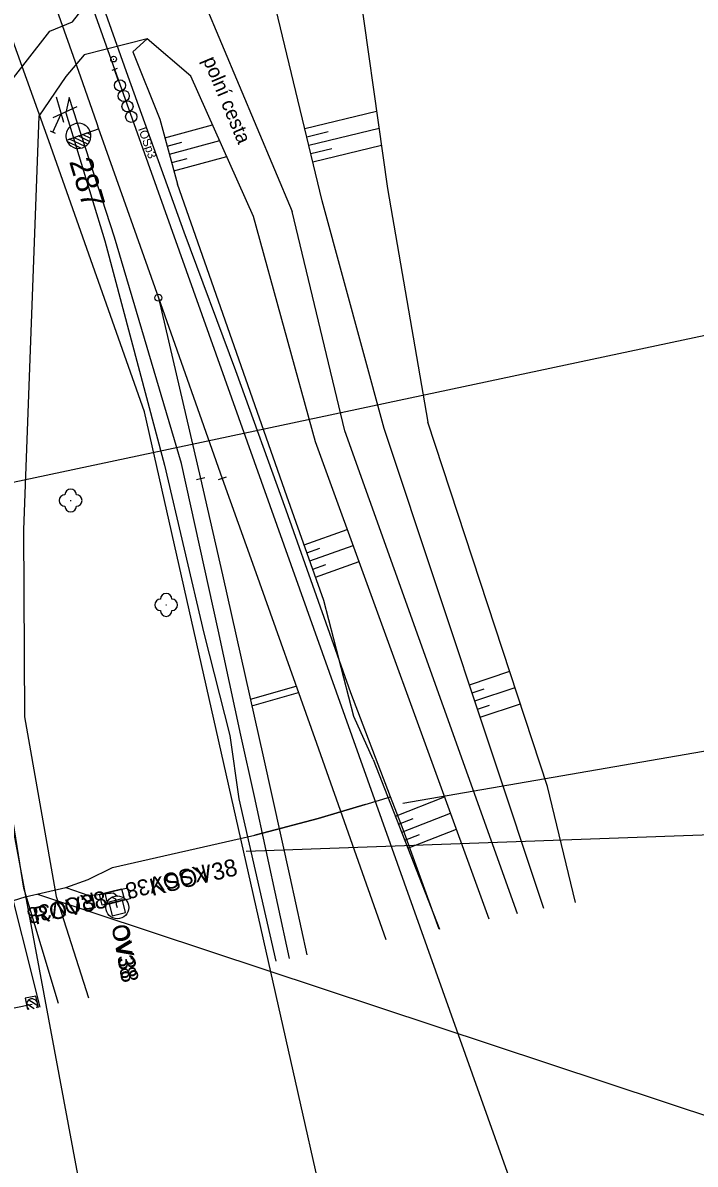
# Model space of a CAD drawing. Extents: x -545967 to -545044, y -1122650 to -1118491.
# Drawn here: x -545696.6 to -545637.8, y -1119258 to -1119158.2 of the extents above; entities that cross this region are included whole.
import ezdxf

# ---------------------------------------------------------------- set-up
doc = ezdxf.new("R2010")
doc.units = 0
for name, color, linetype in [('osvětlené plochy-hodnota-obrys', 7, 'Continuous'), ('Vrstva 1', 7, 'Continuous'), ('Vrstva 11', 7, 'Continuous'), ('Vrstva 11 - Trakce', 7, 'Continuous'), ('Vrstva 12', 7, 'Continuous'), ('Vrstva 12 - Trakce zaklady', 7, 'Continuous'), ('Vrstva 2', 7, 'Continuous'), ('Vrstva 25', 7, 'Continuous'), ('Vrstva 25 - silnoproud prvky', 7, 'Continuous'), ('Vrstva 26', 7, 'Continuous'), ('Vrstva 26 - silnoproud', 7, 'Continuous'), ('Vrstva 28', 7, 'Continuous'), ('Vrstva 4', 7, 'Continuous'), ('Vrstva 48', 7, 'Continuous'), ('Vrstva 49', 7, 'Continuous'), ('Vrstva 50', 7, 'Continuous'), ('Vrstva 51', 7, 'Continuous'), ('Vrstva 6', 7, 'Continuous'), ('Vrstva 63', 7, 'Continuous'), ('Vrstva 7', 7, 'Continuous')]:
    doc.layers.add(name, color=color, linetype=linetype)

msp = doc.modelspace()

# ---------------------------------------------------------------- linework, layer by layer
at = {"layer": 'osvětlené plochy-hodnota-obrys'}
for points in [[(-545694.33, -1119168.5), (-545707.92, -1119130.607), (-545700.794, -1119127.991)], [(-545700.794, -1119127.991), (-545610.463, -1119381.573), (-545628.868, -1119385.178)], [(-545700.341, -1119250.428), (-545705.955, -1119221.665), (-545699.039, -1119220.315), (-545660.607, -1119425.918), (-545653.752, -1119372.856), (-545653.095, -1119348.321), (-545657.119, -1119319.988), (-545685.945, -1119192.198), (-545694.33, -1119168.5)]]:
    msp.add_lwpolyline(points, dxfattribs=at)
at = {"layer": 'Vrstva 1'}
for points in [[(-545730.526, -1119049.438), (-545727.173, -1119060.47), (-545720.468, -1119081.174), (-545711.793, -1119106.078), (-545703.851, -1119128.397), (-545698.023, -1119144.665), (-545693.948, -1119156.135), (-545691.544, -1119162.895), (-545690.154, -1119166.896), (-545689.961, -1119167.438), (-545689.699, -1119168.179), (-545684.737, -1119182.215), (-545679.147, -1119198.024), (-545676.369, -1119205.846), (-545670.918, -1119221.162), (-545664.828, -1119238.335)], [(-545684.737, -1119182.215), (-545681.048, -1119198.017), (-545679.115, -1119206.463), (-545675.534, -1119222.463), (-545673.245, -1119232.849), (-545671.741, -1119239.689)]]:
    msp.add_lwpolyline(points, dxfattribs=at)
at = {"layer": 'Vrstva 11'}
for points in [[(-545693.484, -1119243.944), (-545696.51, -1119233.839), (-545699.129, -1119217.635), (-545699.471, -1119201.94)], [(-545696.533, -1119202.507), (-545696.456, -1119218.879), (-545693.686, -1119234.563), (-545690.855, -1119243.429)]]:
    msp.add_lwpolyline(points, dxfattribs=at)
at = {"layer": 'Vrstva 11 - Trakce'}
for p, q in [((-545695.782, -1119244.029), (-545712.397, -1119247.251)), ((-545696.269, -1119243.934), (-545695.596, -1119244.357)), ((-545696.064, -1119243.62), (-545695.29, -1119244.107))]:
    msp.add_line(p, q, dxfattribs=at)
msp.add_arc((-545695.782, -1119244.029), 0.5, 325.36376, 236.78364, dxfattribs=at)
at = {"layer": 'Vrstva 12'}
msp.add_lwpolyline([(-545687.603, -1119235.974), (-545687.894, -1119234.788), (-545689.08, -1119235.079), (-545688.789, -1119236.265), (-545687.603, -1119235.974)], dxfattribs=at)
at = {"layer": 'Vrstva 12 - Trakce zaklady'}
for points in [[(-545687.603, -1119235.974), (-545687.894, -1119234.788), (-545689.08, -1119235.079), (-545688.789, -1119236.265), (-545687.603, -1119235.974)], [(-545695.23, -1119244.286), (-545695.454, -1119243.299), (-545696.392, -1119243.46)], [(-545696.392, -1119243.46), (-545696.174, -1119244.47)]]:
    msp.add_lwpolyline(points, dxfattribs=at)
at = {"layer": 'Vrstva 2'}
for p, q in [((-545692.765, -1119168.432), (-545690.695, -1119167.7)), ((-545692.764, -1119168.433), (-545692.765, -1119168.432)), ((-545692.76, -1119168.438), (-545689.961, -1119167.438)), ((-545691.148, -1119168.994), (-545692.512, -1119168.343)), ((-545690.909, -1119168.792), (-545692.132, -1119168.208)), ((-545690.749, -1119168.553), (-545691.752, -1119168.074)), ((-545690.655, -1119168.282), (-545691.372, -1119167.94)), ((-545690.638, -1119167.974), (-545690.992, -1119167.805)), ((-545691.505, -1119169.139), (-545692.704, -1119168.567)), ((-545684.737, -1119182.215), (-545681.048, -1119198.017)), ((-545681.414, -1119198.099), (-545680.682, -1119197.935)), ((-545678.794, -1119197.898), (-545679.5, -1119198.15))]:
    msp.add_line(p, q, dxfattribs=at)
msp.add_lwpolyline([(-545689.961, -1119167.438), (-545689.699, -1119168.179), (-545684.737, -1119182.215), (-545679.147, -1119198.024)], dxfattribs=at)
msp.add_circle((-545684.737, -1119182.215), 0.3, dxfattribs=at)
for centre, radius, start, end in [((-545691.729, -1119168.065), 1.097, 19.42224, 199.89176), ((-545691.729, -1119168.066), 1.098, 199.51177, 19.47262)]:
    msp.add_arc(centre, radius, start, end, dxfattribs=at)
at = {"layer": 'Vrstva 25'}
for points in [[(-545689.652, -1119235.344), (-545689.89, -1119234.373), (-545687.948, -1119233.896), (-545687.71, -1119234.867), (-545689.652, -1119235.344)], [(-545687.448, -1119233.816), (-545687.21, -1119234.787), (-545689.152, -1119235.264), (-545689.39, -1119234.293), (-545687.448, -1119233.816)]]:
    msp.add_lwpolyline(points, dxfattribs=at)
msp.add_circle((-545688.326, -1119235.53), 1, dxfattribs=at)
at = {"layer": 'Vrstva 25 - silnoproud prvky'}
for points in [[(-545689.652, -1119235.344), (-545689.89, -1119234.373), (-545687.948, -1119233.896), (-545687.71, -1119234.867), (-545689.652, -1119235.344)], [(-545687.448, -1119233.816), (-545687.21, -1119234.787), (-545689.152, -1119235.264), (-545689.39, -1119234.293), (-545687.448, -1119233.816)]]:
    msp.add_lwpolyline(points, dxfattribs=at)
msp.add_circle((-545688.326, -1119235.53), 1, dxfattribs=at)
at = {"layer": 'Vrstva 26'}
for points in [[(-545660.174, -1119237.425), (-545663.331, -1119228.723), (-545664.431, -1119225.855), (-545667.915, -1119216.776), (-545673.57, -1119200.8), (-545677.95, -1119188.599), (-545682.479, -1119176.492), (-545687.385, -1119162.872), (-545691.436, -1119151.431), (-545691.75, -1119150.64)], [(-545687.385, -1119162.872), (-545691.436, -1119151.431)], [(-545698.841, -1119235.301), (-545698.529, -1119235.274), (-545696.399, -1119234.598), (-545692.825, -1119233.775), (-545690.864, -1119233.076), (-545688.738, -1119232.03), (-545676.291, -1119229.209), (-545675.638, -1119229.038), (-545670.747, -1119227.759), (-545668.794, -1119227.17), (-545666.647, -1119226.523), (-545664.431, -1119225.855)], [(-545666.647, -1119226.523), (-545668.794, -1119227.17), (-545670.747, -1119227.759), (-545675.638, -1119229.038), (-545676.291, -1119229.209)], [(-545692.825, -1119233.775), (-545690.82, -1119234.48), (-545688.66, -1119234.25), (-545688.3, -1119234.54), (-545688.8, -1119234.62), (-545688.49, -1119234.77), (-545688.44, -1119235.29), (-545688.326, -1119235.529), (-545688.326, -1119235.53)]]:
    msp.add_lwpolyline(points, dxfattribs=at)
at = {"layer": 'Vrstva 26 - silnoproud'}
for points in [[(-545660.174, -1119237.425), (-545663.331, -1119228.723), (-545664.431, -1119225.855), (-545667.915, -1119216.776), (-545673.57, -1119200.8), (-545677.95, -1119188.599), (-545682.479, -1119176.492), (-545687.385, -1119162.872), (-545691.436, -1119151.431), (-545691.75, -1119150.64)], [(-545687.385, -1119162.872), (-545691.436, -1119151.431)], [(-545708.67, -1119197.64), (-545708.32, -1119197.58), (-545708.6, -1119196.51), (-545704.54, -1119197.6), (-545702.23, -1119206.95), (-545699.9, -1119221.45), (-545698.219, -1119231.843), (-545695.098, -1119244.26)], [(-545698.841, -1119235.301), (-545698.529, -1119235.274), (-545696.399, -1119234.598), (-545692.825, -1119233.775), (-545690.864, -1119233.076), (-545688.738, -1119232.03), (-545676.291, -1119229.209), (-545675.638, -1119229.038), (-545670.747, -1119227.759), (-545668.794, -1119227.17), (-545666.647, -1119226.523), (-545664.431, -1119225.855)], [(-545666.647, -1119226.523), (-545668.794, -1119227.17), (-545670.747, -1119227.759), (-545675.638, -1119229.038), (-545676.291, -1119229.209)], [(-545692.825, -1119233.775), (-545690.82, -1119234.48), (-545688.66, -1119234.25), (-545688.3, -1119234.54), (-545688.8, -1119234.62), (-545688.49, -1119234.77), (-545688.44, -1119235.29), (-545688.326, -1119235.529), (-545688.326, -1119235.53)]]:
    msp.add_lwpolyline(points, dxfattribs=at)
at = {"layer": 'Vrstva 28'}
msp.add_line((-545688.678, -1119161.351), (-545688.628, -1119161.351), dxfattribs=at)
msp.add_circle((-545688.653, -1119161.351), 0.25, dxfattribs=at)
at = {"layer": 'Vrstva 4'}
for p, q in [((-545693.948, -1119156.135), (-545691.544, -1119162.895)), ((-545693.667, -1119164.657), (-545693.034, -1119166.873)), ((-545693.978, -1119167.733), (-545693.248, -1119166.142)), ((-545693.943, -1119166.457), (-545691.85, -1119165.491)), ((-545694.205, -1119167.629), (-545693.751, -1119167.837))]:
    msp.add_line(p, q, dxfattribs=at)
for points in [[(-545682.722, -1119196.715), (-545688.56, -1119176.928), (-545692.538, -1119164.711), (-545692.829, -1119166.04), (-545689.41, -1119177.241), (-545684.189, -1119196.85), (-545680.751, -1119211.563), (-545678.475, -1119220.498)], [(-545673.268, -1119239.987), (-545676.336, -1119225.824), (-545677.525, -1119220.471), (-545679.503, -1119211.27), (-545682.722, -1119196.715)], [(-545678.475, -1119220.498), (-545677.708, -1119226.035), (-545674.475, -1119240.224)]]:
    msp.add_lwpolyline(points, dxfattribs=at)
at = {"layer": 'Vrstva 48'}
for p, q in [((-545671.927, -1119167.414), (-545665.647, -1119165.898)), ((-545684.16, -1119168.233), (-545679.991, -1119167.099)), ((-545671.574, -1119168.872), (-545665.435, -1119167.39)), ((-545671.75, -1119168.143), (-545669.888, -1119167.693)), ((-545683.963, -1119168.956), (-545682.679, -1119168.607)), ((-545683.766, -1119169.68), (-545679.373, -1119168.485)), ((-545671.398, -1119169.601), (-545669.577, -1119169.162)), ((-545671.222, -1119170.33), (-545665.222, -1119168.881)), ((-545683.569, -1119170.404), (-545682.218, -1119170.036)), ((-545683.372, -1119171.128), (-545678.755, -1119169.872)), ((-545671.995, -1119203.823), (-545668.209, -1119202.472)), ((-545671.743, -1119204.529), (-545670.606, -1119204.124)), ((-545671.491, -1119205.236), (-545667.696, -1119203.882)), ((-545670.987, -1119206.649), (-545667.183, -1119205.292)), ((-545671.239, -1119205.942), (-545670.099, -1119205.536)), ((-545657.535, -1119216.057), (-545654.01, -1119214.886)), ((-545657.062, -1119217.48), (-545653.542, -1119216.311)), ((-545657.298, -1119216.769), (-545656.242, -1119216.418)), ((-545656.826, -1119218.192), (-545655.77, -1119217.842)), ((-545656.589, -1119218.904), (-545653.074, -1119217.736)), ((-545664.001, -1119227.551), (-545659.699, -1119225.869)), ((-545663.455, -1119228.948), (-545659.186, -1119227.279)), ((-545663.728, -1119228.249), (-545662.442, -1119227.747)), ((-545663.182, -1119229.646), (-545661.906, -1119229.148)), ((-545662.909, -1119230.345), (-545658.673, -1119228.689))]:
    msp.add_line(p, q, dxfattribs=at)
at = {"layer": 'Vrstva 49'}
for points in [[(-545675.226, -1119153.753), (-545667.594, -1119152.222), (-545664.683, -1119172.67), (-545661.167, -1119193.097)], [(-545651.031, -1119235.635), (-545664.976, -1119193.655), (-545670.399, -1119173.739), (-545675.226, -1119153.753)], [(-545685.704, -1119159.567), (-545686.973, -1119160.727), (-545684.605, -1119166.595), (-545683.057, -1119172.287)], [(-545655.806, -1119236.57), (-545670.996, -1119194.81), (-545676.417, -1119175.121), (-545681.891, -1119162.833), (-545685.704, -1119159.567)], [(-545665.935, -1119222.602), (-545667.654, -1119218.849), (-545670.261, -1119208.684), (-545673.512, -1119199.57), (-545683.057, -1119172.287)], [(-545648.239, -1119235.089), (-545650.699, -1119224.967), (-545661.167, -1119193.097)], [(-545665.935, -1119222.602), (-545660.145, -1119237.419)]]:
    msp.add_lwpolyline(points, dxfattribs=at)
at = {"layer": 'Vrstva 50'}
for p, q in [((-545692.439, -1119199.95), (-545692.368, -1119199.95)), ((-545684.084, -1119209.08), (-545684.012, -1119209.08))]:
    msp.add_line(p, q, dxfattribs=at)
for centre, start, end in [((-545692.41, -1119199.449), 0, 180), ((-545692.91, -1119199.949), 90, 270), ((-545691.91, -1119199.949), 270, 90), ((-545692.41, -1119200.449), 180, 0), ((-545684.054, -1119208.579), 0, 180), ((-545684.554, -1119209.079), 90, 270), ((-545683.554, -1119209.079), 270, 90), ((-545684.054, -1119209.579), 180, 0)]:
    msp.add_arc(centre, 0.5, start, end, dxfattribs=at)
at = {"layer": 'Vrstva 51'}
for points in [[(-545699.471, -1119201.94), (-545698.549, -1119164.446), (-545694.235, -1119158.917), (-545692.241, -1119158.084), (-545688.341, -1119153.091), (-545685.062, -1119149.37), (-545681.978, -1119143.375)], [(-545679.27, -1119144.734), (-545681.865, -1119150.517), (-545680.757, -1119156.324), (-545673.045, -1119174.666)], [(-545676.417, -1119175.121), (-545681.891, -1119162.833), (-545685.704, -1119159.567), (-545691.222, -1119160.972), (-545692.83, -1119162.884), (-545695.181, -1119166.34), (-545696.533, -1119202.507)], [(-545655.806, -1119236.57), (-545670.996, -1119194.81), (-545676.417, -1119175.121)], [(-545653.315, -1119236.082), (-545668.43, -1119193.867), (-545673.045, -1119174.666)]]:
    msp.add_lwpolyline(points, dxfattribs=at)
at = {"layer": 'Vrstva 6'}
for p, q in [((-545688.35, -1119162.184), (-545688.821, -1119162.351)), ((-545688.253, -1119163.2), (-545688.585, -1119162.268))]:
    msp.add_line(p, q, dxfattribs=at)
for centre in [(-545688.09, -1119163.657), (-545687.763, -1119164.572), (-545687.437, -1119165.486), (-545687.111, -1119166.401)]:
    msp.add_circle(centre, 0.486, dxfattribs=at)
at = {"layer": 'Vrstva 63'}
for p, q in [((-545607.451, -1119179.265), (-545702.192, -1119199.374)), ((-545600.352, -1119215.539), (-545663.35, -1119226.444)), ((-545597.957, -1119227.774), (-545677.045, -1119230.655)), ((-545589.819, -1119269.354), (-545695.286, -1119234.415))]:
    msp.add_line(p, q, dxfattribs=at)
at = {"layer": 'Vrstva 7'}
for p, q in [((-545676.683, -1119217.329), (-545672.692, -1119216.177)), ((-545676.552, -1119217.916), (-545672.491, -1119216.743))]:
    msp.add_line(p, q, dxfattribs=at)

# ---------------------------------------------------------------- texts
at = {"layer": 'Vrstva 2'}
msp.add_text('287', height=2, rotation=286.78427, dxfattribs=at).set_placement((-545692.554, -1119170.3))
at = {"layer": 'Vrstva 25'}
for s, rotation, p in [('KSOV38', 13.7859, (-545685.285, -1119234.54)), ('ROV38', 13.7859, (-545695.496, -1119237.047)), ('OV38', 280.61663, (-545688.844, -1119237.154))]:
    msp.add_text(s, height=1.5, rotation=rotation, dxfattribs=at).set_placement(p)
at = {"layer": 'Vrstva 25 - silnoproud prvky'}
for s, rotation, p in [('KSOV38', 193.7859, (-545680.65, -1119231.731)), ('ROV38', 193.7859, (-545690.382, -1119234.182)), ('OV38', 280.61663, (-545688.844, -1119237.154))]:
    msp.add_text(s, height=1.4, rotation=rotation, dxfattribs=at).set_placement(p)
at = {"layer": 'Vrstva 51'}
msp.add_text('polní cesta', height=1.25, rotation=292.8046, dxfattribs=at).set_placement((-545680.862, -1119161.426))
at = {"layer": 'Vrstva 6'}
msp.add_text('IOSp3', height=0.75, rotation=289.58761, dxfattribs=at).set_placement((-545686.525, -1119167.451))

doc.saveas('drawing.dxf')
